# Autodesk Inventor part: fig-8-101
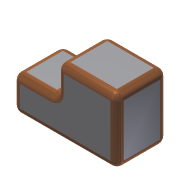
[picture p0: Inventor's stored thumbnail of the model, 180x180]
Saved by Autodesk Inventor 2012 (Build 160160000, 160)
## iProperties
Shininess: 64.0
Length Units: 11269
Angle Units: 11279
Time Units: 11290
Mass Units: 11283
Length Display Precision: 3
Angle Display Precision: 2
Compacted: True
Part Number: fig-8-101
Document SubType Name: Modeling
Created: 2002-12
Designer: deepak
Density: 1 g/cm^3
Material: Default
Density: 0.0
Volumn: 0.0
Area: 0.0
PropertySet Name: Model Information
Control State: 0
Master: False
Checked Out: False
Author: deepak
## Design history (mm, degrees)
sketch "Sketch1"
  geometry: L1 (-26.972, 23.346)-(8.906, 23.346); L2 (8.906, 23.346)-(8.906, 5.025); L3 (8.906, -15.84)-(-26.972, -15.84); L4 (-26.972, -15.84)-(-26.972, 23.346); L5 (8.906, -15.84)-(35.369, -15.84); L6 (35.369, -15.84)-(35.369, 5.025); L7 (35.369, 5.025)-(8.906, 5.025)
  constraints: 14 end point, 3 parallel, 2 horizontal, 2 perpendicular
extrude "Extrusion1" new body sketch "Sketch1" stored distance "d0" = 30; taper "d1" = 0 deg
fillet "Fillet1" dims "d2" = 4, "d3" = 4
body "Solid1"
